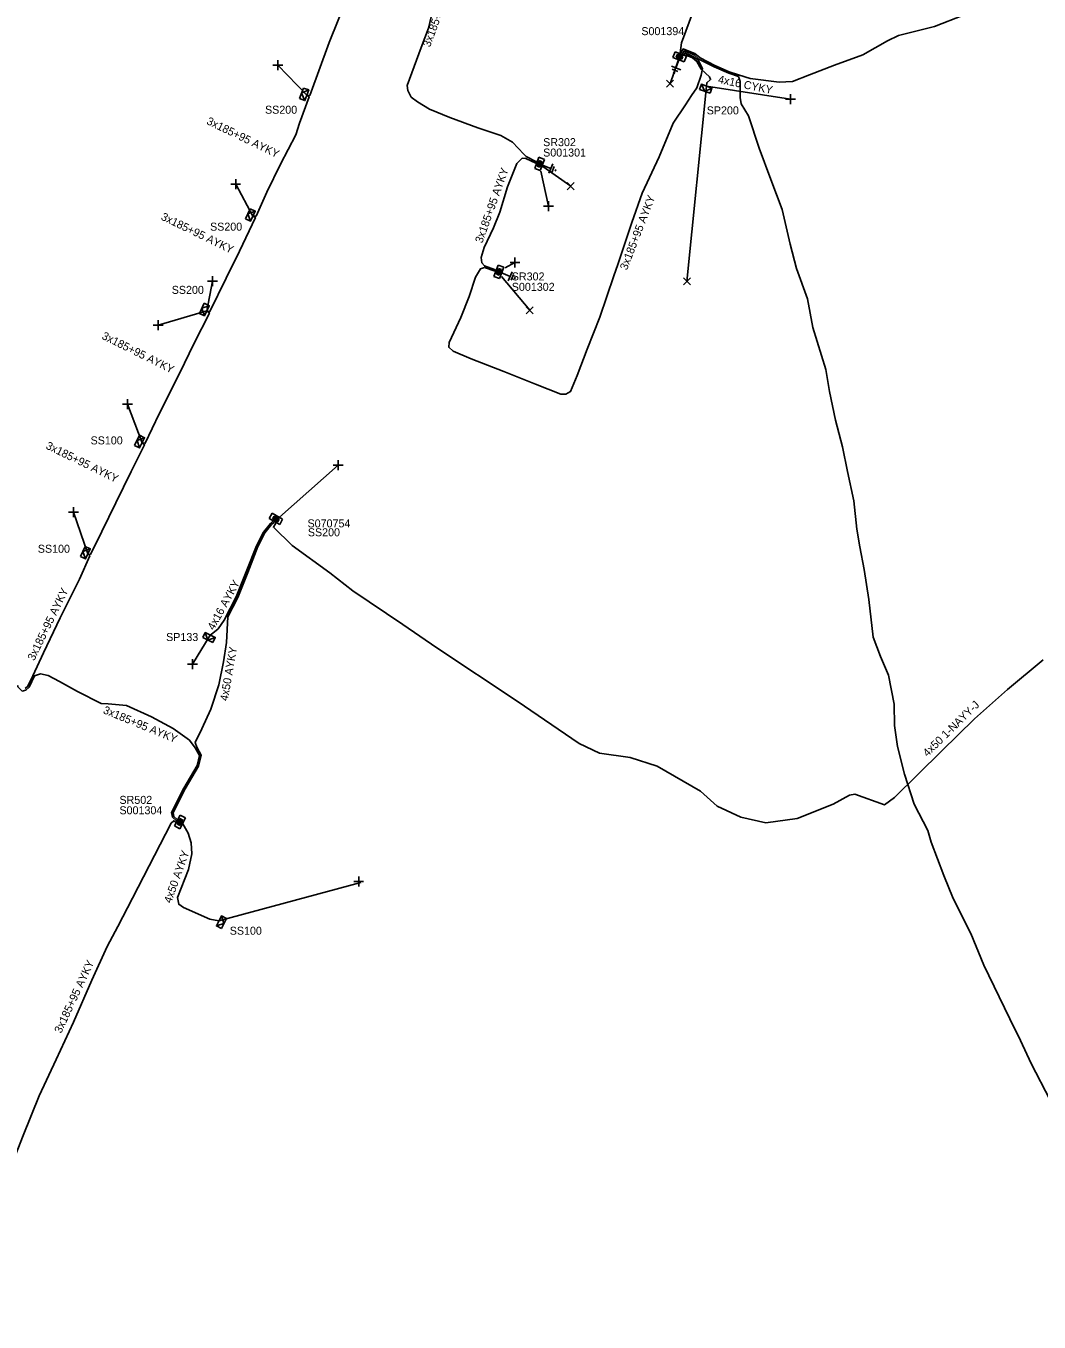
# Model space of a CAD drawing. Extents: x -763093 to -760976, y -1155572 to -1152009.
# Drawn here: x -762038.5 to -761911.9, y -1155041.4 to -1154879.5 of the extents above; entities that cross this region are included whole.
import ezdxf

# ---------------------------------------------------------------- set-up
doc = ezdxf.new("R2010")
doc.units = 0
for name, color, linetype in [('Vrstva 1', 7, 'Continuous'), ('Vrstva 14', 7, 'Continuous'), ('Vrstva 15', 7, 'Continuous'), ('Vrstva 28', 7, 'Continuous'), ('Vrstva 29', 7, 'Continuous'), ('Vrstva 30', 7, 'Continuous'), ('Vrstva 31', 7, 'Continuous'), ('Vrstva 33', 7, 'Continuous'), ('Vrstva 34', 7, 'Continuous'), ('Vrstva 5', 7, 'Continuous'), ('Vrstva 52', 7, 'Continuous'), ('Vrstva 54', 7, 'Continuous'), ('Vrstva 59', 7, 'Continuous'), ('Vrstva 6', 7, 'Continuous'), ('Vrstva 8', 7, 'Continuous'), ('Vrstva 9', 7, 'Continuous')]:
    doc.layers.add(name, color=color, linetype=linetype)

# ---------------------------------------------------------------- blocks, each defined once
blk = doc.blocks.new('NN800')
at = {"layer": 'Vrstva 1'}
for points in [[(-0.44, 0.44), (0.44, -0.44)], [(-0.44, -0.44), (0.44, 0.44)]]:
    blk.add_lwpolyline(points, dxfattribs=at)
blk = doc.blocks.new('NN620')
at = {"layer": 'Vrstva 8'}
for points in [[(0.75, 0), (-0.75, 0)], [(-0.75, 0), (-0.75, -0.75)], [(0.75, -0.75), (0.75, 0)], [(-0.75, -0.75), (0.75, -0.75)], [(0.37, -0.18), (-0.38, -0.18)], [(-0.38, -0.18), (-0.38, -0.56)], [(-0.38, -0.56), (0.37, -0.56)], [(0.32, -0.23), (-0.33, -0.23)], [(-0.33, -0.23), (-0.33, -0.51)], [(-0.33, -0.51), (0.32, -0.51)], [(0.27, -0.27), (-0.28, -0.27)], [(-0.28, -0.27), (-0.28, -0.46)], [(-0.28, -0.46), (0.27, -0.46)], [(0.23, -0.32), (-0.23, -0.32)], [(-0.23, -0.32), (-0.23, -0.42)], [(-0.23, -0.42), (0.23, -0.42)], [(-0.19, -0.37), (0.19, -0.37)], [(0.23, -0.42), (0.23, -0.32)], [(0.27, -0.46), (0.27, -0.27)], [(0.32, -0.51), (0.32, -0.23)], [(0.37, -0.56), (0.37, -0.18)]]:
    blk.add_lwpolyline(points, dxfattribs=at)
blk = doc.blocks.new('NN630')
at = {"layer": 'Vrstva 9'}
for points in [[(0, -0.7), (-0.7, 0)], [(-0.7, -0.7), (-0.7, 0), (0.7, 0), (0.7, -0.7)], [(-0.7, -0.7), (0.7, -0.7)], [(0, -0.7), (0.7, 0)]]:
    blk.add_lwpolyline(points, dxfattribs=at)
blk = doc.blocks.new('NN810')
at = {"layer": 'Vrstva 14'}
for points in [[(0, -0.64), (0, -1.89)], [(0.63, -1.89), (-0.62, -1.89)], [(0.39, -2.2), (-0.4, -2.2)], [(0, -2.52), (-0.12, -2.52)], [(0.14, -2.52), (0, -2.52)]]:
    blk.add_lwpolyline(points, dxfattribs=at)

msp = doc.modelspace()

# ---------------------------------------------------------------- linework, layer by layer
at = {"layer": 'Vrstva 5'}
for points in [[(-761974.73, -1154896.45), (-761976.02, -1154895.81), (-761976.32, -1154895.51), (-761977.72, -1154894), (-761979.19, -1154893.19), (-761982.07, -1154892.21), (-761985.55, -1154890.91), (-761988.08, -1154889.86), (-761989.57, -1154888.98), (-761990.38, -1154888.36), (-761990.79, -1154887.53), (-761990.9, -1154886.94), (-761989.13, -1154882.18), (-761988.22, -1154879.75), (-761987.67, -1154877.45), (-761987.55, -1154876.02), (-761986.41, -1154872.5), (-761984.64, -1154867.37), (-761984.51, -1154867.33)], [(-761953.59, -1154873.47), (-761956.61, -1154881.61), (-761956.77, -1154882.82)], [(-761956.76, -1154882.91), (-761956.39, -1154882.34), (-761954.93, -1154882.94), (-761954.29, -1154883.46), (-761952.44, -1154884.41), (-761950.63, -1154885.21), (-761949.5, -1154885.6), (-761948.02, -1154886.05), (-761944.39, -1154886.5), (-761942.75, -1154886.42), (-761940.62, -1154885.57), (-761937.48, -1154884.38), (-761933.96, -1154883.07), (-761930.85, -1154881.32), (-761929.51, -1154880.69), (-761924.98, -1154879.55), (-761921.37, -1154878.15), (-761917.08, -1154876.64), (-761913.14, -1154874.9), (-761909.53, -1154873.22)], [(-762038.62, -1154962.29), (-762038.28, -1154962), (-762037.67, -1154960.67), (-762036.31, -1154957.82), (-762034.25, -1154953.43), (-762031.84, -1154948.59), (-762030.54, -1154945.69), (-762030.77, -1154945.44), (-762030.46, -1154945.51), (-762029.04, -1154942.66), (-762027.29, -1154939.07), (-762025.35, -1154935.17), (-762023.69, -1154931.81), (-762024, -1154931.57), (-762023.61, -1154931.63), (-762021.86, -1154927.96), (-762019.29, -1154922.81), (-762017.53, -1154919.2), (-762015.6, -1154915.35), (-762015.91, -1154915.07), (-762015.52, -1154915.17), (-762013.49, -1154911), (-762011.84, -1154907.64), (-762009.84, -1154903.41), (-762010.16, -1154903.25), (-762009.76, -1154903.23), (-762008.43, -1154900.25), (-762006.69, -1154896.74), (-762004.79, -1154893.07), (-762004.33, -1154891.63), (-762003.12, -1154888.34), (-762003.42, -1154888.14), (-762003.06, -1154888.16), (-762000.61, -1154881.53), (-761998.29, -1154875.7)], [(-761979.77, -1154910.07), (-761980.01, -1154910.09), (-761981.22, -1154909.65), (-761981.7, -1154909.83), (-761982.33, -1154910.89), (-761983.14, -1154913.28), (-761984.18, -1154915.92), (-761985.65, -1154919.02), (-761985.69, -1154919.64), (-761985.14, -1154920.13), (-761982.87, -1154921.06), (-761978.81, -1154922.64), (-761974.86, -1154924.23), (-761971.7, -1154925.51), (-761971.05, -1154925.5), (-761970.47, -1154925.16), (-761969.62, -1154923.17), (-761968.39, -1154919.89), (-761966.82, -1154915.85), (-761965.05, -1154910.71), (-761964.55, -1154909.27), (-761962.83, -1154904.06), (-761961.5, -1154900.37), (-761959.38, -1154895.82), (-761957.66, -1154891.63), (-761956.09, -1154889.33), (-761955.36, -1154888.18), (-761954.68, -1154887.23), (-761954.16, -1154885.64), (-761953.96, -1154884.8), (-761954.54, -1154883.77), (-761955.13, -1154883.29), (-761956.19, -1154882.86), (-761956.33, -1154883.07)], [(-761956.14, -1154883.15), (-761956.11, -1154883.11), (-761955.23, -1154883.46), (-761954.67, -1154883.92), (-761954.14, -1154884.88), (-761953.1, -1154885.82), (-761952.96, -1154886.19), (-761953.44, -1154886.58), (-761953.46, -1154887)], [(-761979.77, -1154910.07), (-761979.95, -1154909.9), (-761981.22, -1154909.44), (-761981.55, -1154909.08), (-761981.63, -1154908.4), (-761981.28, -1154907.17), (-761980.11, -1154904.7), (-761979.3, -1154902.77), (-761978.36, -1154899.58), (-761977.18, -1154896.68), (-761976.52, -1154896.02), (-761976.04, -1154896.03), (-761974.81, -1154896.64)], [(-762019.61, -1154978.63), (-762020.04, -1154978.25), (-762020.12, -1154977.8), (-762018.6, -1154974.83), (-762016.95, -1154971.99), (-762016.61, -1154970.61), (-762017.18, -1154969.62), (-762017.37, -1154969.01), (-762016.52, -1154967.33), (-762015.4, -1154964.85), (-762014.42, -1154961.81), (-762013.85, -1154958.92), (-762013.47, -1154956.51), (-762013.3, -1154953.31), (-762012.06, -1154950.89), (-762010.81, -1154947.76), (-762009.54, -1154944.51), (-762008.66, -1154942.83), (-762007.82, -1154941.78), (-762007.51, -1154941.5)], [(-762015.49, -1154955.59), (-762015.15, -1154955.34), (-762014.48, -1154954.81), (-762013.74, -1154953.73), (-762012.25, -1154950.83), (-762010.99, -1154947.68), (-762009.72, -1154944.43), (-762008.82, -1154942.73), (-762007.96, -1154941.64), (-762007.89, -1154941.57), (-762007.67, -1154941.38)], [(-762039.5, -1154961.9), (-762039.57, -1154962.01), (-762039, -1154962.59), (-762038.52, -1154962.47), (-762038.12, -1154962.12), (-762037.45, -1154960.67), (-762036.71, -1154960.42), (-762035.72, -1154960.66), (-762034.33, -1154961.38), (-762032.07, -1154962.66), (-762029.12, -1154964.13), (-762028.23, -1154964.18), (-762025.96, -1154964.41), (-762022.84, -1154965.82), (-762020.14, -1154967.27), (-762018.08, -1154968.71), (-762017.37, -1154969.7), (-762016.83, -1154970.65), (-762017.13, -1154971.91), (-762018.78, -1154974.73), (-762020.32, -1154977.76), (-762020.22, -1154978.35), (-762019.7, -1154978.82)], [(-762048.47, -1155043.02), (-762046.66, -1155038.38), (-762044.82, -1155033.57), (-762042.9, -1155028.86), (-762041.22, -1155024.21), (-762038.87, -1155018.14), (-762036.88, -1155013.17), (-762034.76, -1155008.65), (-762032.58, -1155003.98), (-762030.27, -1154998.71), (-762028.37, -1154994.51), (-762027.03, -1154992.02), (-762025.2, -1154988.46), (-762020.35, -1154979.1), (-762020.05, -1154978.79), (-762019.77, -1154978.99)], [(-762018.93, -1154979.18), (-762018.23, -1154980.33), (-762017.89, -1154981.56), (-762017.8, -1154982.95), (-762018.22, -1154984.91), (-762019.57, -1154988.41), (-762019.43, -1154989.23), (-762018.84, -1154989.63), (-762015.55, -1154991.09), (-762014.41, -1154991.31)]]:
    msp.add_lwpolyline(points, dxfattribs=at)
at = {"layer": 'Vrstva 52'}
msp.add_lwpolyline([(-762007.25, -1154941.54), (-762007.59, -1154942.13), (-762005.24, -1154944.42), (-762000.54, -1154947.82), (-761997.69, -1154950.08), (-761991.43, -1154954.26), (-761987.17, -1154957.2), (-761977.12, -1154963.85), (-761969.38, -1154969.13), (-761966.87, -1154970.37), (-761963.03, -1154970.9), (-761959.66, -1154971.99), (-761954.24, -1154975.09), (-761952.13, -1154976.97), (-761949.2, -1154978.35), (-761946.06, -1154979.07), (-761942.17, -1154978.53), (-761937.64, -1154976.71), (-761935.61, -1154975.59), (-761934.96, -1154975.49), (-761931.24, -1154976.79), (-761929.98, -1154975.88), (-761924.1, -1154970.12), (-761920.01, -1154966.08), (-761915.86, -1154962.39), (-761911.4, -1154958.7)], dxfattribs=at)
at = {"layer": 'Vrstva 59'}
for points in [[(-762003.42, -1154888.14), (-762007.06, -1154884.38)], [(-761957.01, -1154883.81), (-761958.03, -1154886.7)], [(-761953.46, -1154887), (-761955.92, -1154911.4)], [(-761953.46, -1154887), (-761943, -1154888.63)], [(-761974.18, -1154897.61), (-761973.22, -1154902.01)], [(-761973.91, -1154897.03), (-761970.44, -1154899.5)], [(-762010.16, -1154903.25), (-762012.31, -1154899.25)], [(-761978.65, -1154909.72), (-761977.41, -1154909.05)], [(-761979.1, -1154910.77), (-761975.56, -1154915)], [(-762015.91, -1154915.07), (-762015.21, -1154911.38)], [(-762015.91, -1154915.07), (-762022, -1154916.88)], [(-762024, -1154931.57), (-762025.81, -1154926.75)], [(-762006.85, -1154940.86), (-761999.5, -1154934.38)], [(-762030.77, -1154945.44), (-762032.56, -1154940.25)], [(-762015.49, -1154955.59), (-762017.72, -1154959.25)], [(-762014.41, -1154991.31), (-761996.67, -1154986.51)]]:
    msp.add_lwpolyline(points, dxfattribs=at)
at = {"layer": 'Vrstva 9'}
msp.add_lwpolyline([(-761956.52, -1154882.97), (-761956.28, -1154882.61), (-761955.03, -1154883.11), (-761954.42, -1154883.61), (-761952.52, -1154884.59), (-761950.71, -1154885.39), (-761949.49, -1154885.81), (-761949.28, -1154886.42), (-761949.28, -1154888.42), (-761949.15, -1154889.21), (-761948.23, -1154890.72), (-761946.9, -1154894.74), (-761945.45, -1154898.66), (-761944.02, -1154902.41), (-761943.02, -1154906.73), (-761942.23, -1154909.78), (-761940.87, -1154913.56), (-761940.21, -1154917.16), (-761938.57, -1154922.42), (-761938.11, -1154925.14), (-761937.38, -1154928.73), (-761936.47, -1154932.07), (-761935.88, -1154935.14), (-761935.06, -1154938.82), (-761934.68, -1154942.35), (-761934.34, -1154944.56), (-761933.79, -1154947.41), (-761933.19, -1154951.16), (-761932.64, -1154955.84), (-761931.72, -1154958.29), (-761930.74, -1154960.62), (-761930.03, -1154964.24), (-761929.98, -1154966.91), (-761929.63, -1154969.54), (-761928.72, -1154972.96), (-761927.55, -1154976.72), (-761925.83, -1154980.03), (-761925.39, -1154981.49), (-761923.82, -1154985.66), (-761922.64, -1154988.5), (-761920.45, -1154992.9), (-761918.82, -1154996.84), (-761916.91, -1155000.81), (-761915.56, -1155003.56), (-761914.24, -1155006.24), (-761912.93, -1155009.14), (-761910.54, -1155013.72)], dxfattribs=at)

# ---------------------------------------------------------------- block references
at = {"layer": 'Vrstva 15'}
for p, rotation in [((-761956.61, -1154882.96), -21.18706123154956), ((-761974.68, -1154896.59), 68.01475553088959), ((-761979.77, -1154910.07), 68.17776944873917)]:
    msp.add_blockref('NN810', p, dxfattribs=dict(at, rotation=rotation))
at = {"layer": 'Vrstva 28'}
for p, rotation in [((-761956.7, -1154882.99), -20.859961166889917), ((-761974.68, -1154896.59), 69.35043834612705), ((-761979.77, -1154910.07), 68.78385000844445), ((-762007.46, -1154941.4), 150.68999166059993), ((-762019.6, -1154978.78), 62.94315283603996)]:
    msp.add_blockref('NN620', p, dxfattribs=dict(at, rotation=rotation))
at = {"layer": 'Vrstva 31'}
for p, rotation in [((-761953.46, -1154887), -19.580859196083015), ((-762003.42, -1154888.14), -110.18468059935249), ((-762010.16, -1154903.25), -115.93255558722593), ((-762015.91, -1154915.07), -115.93255552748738), ((-762024, -1154931.57), -115.94291108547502), ((-762030.77, -1154945.44), -114.37115145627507), ((-762015.49, -1154955.59), -25.793149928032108), ((-762014.41, -1154991.31), 63.191864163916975)]:
    msp.add_blockref('NN630', p, dxfattribs=dict(at, rotation=rotation))
at = {"layer": 'Vrstva 34'}
for p, rotation in [((-762007.06, -1154884.38), 45), ((-761943, -1154888.63), 45), ((-762012.31, -1154899.25), 45), ((-761973.22, -1154902.01), 45), ((-761977.41, -1154909.05), 45), ((-762015.21, -1154911.38), 45), ((-762022, -1154916.88), 45), ((-762025.81, -1154926.75), 45), ((-761999.5, -1154934.38), 45), ((-762032.56, -1154940.25), 45), ((-762017.72, -1154959.25), 45), ((-761996.94, -1154986.38), 44.99999995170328)]:
    msp.add_blockref('NN800', p, dxfattribs=dict(at, rotation=rotation))
for p in [(-761958.03, -1154886.7), (-761970.44, -1154899.5), (-761955.92, -1154911.4), (-761975.56, -1154915)]:
    msp.add_blockref('NN800', p, dxfattribs=at)

# ---------------------------------------------------------------- texts
at = {"layer": 'Vrstva 29'}
for s, p in [('S001394', (-761961.62, -1154880.63)), ('S001301', (-761973.89, -1154895.8)), ('S001302', (-761977.81, -1154912.58)), ('S070754', (-762003.33, -1154942.14)), ('S001304', (-762026.83, -1154977.99))]:
    msp.add_text(s, height=1, dxfattribs=at).set_placement(p)
at = {"layer": 'Vrstva 30'}
for s, p in [('SR302', (-761973.89, -1154894.5)), ('SR302', (-761977.81, -1154911.28)), ('SS200', (-762003.29, -1154943.25)), ('SR502', (-762026.83, -1154976.69))]:
    msp.add_text(s, height=1, dxfattribs=at).set_placement(p)
at = {"layer": 'Vrstva 33'}
for s, p in [('SS200', (-762008.64, -1154890.45)), ('SP200', (-761953.45, -1154890.53)), ('SS200', (-762015.51, -1154905.06)), ('SS200', (-762020.3, -1154912.96)), ('SS100', (-762030.44, -1154931.77)), ('SS100', (-762037.03, -1154945.31)), ('SP133', (-762021, -1154956.34)), ('SS100', (-762013.05, -1154993.04))]:
    msp.add_text(s, height=1, dxfattribs=at).set_placement(p)
at = {"layer": 'Vrstva 54'}
msp.add_text('4x50 1-NAYY-J', height=1, rotation=44.409, dxfattribs=at).set_placement((-761925.87, -1154970.87))
at = {"layer": 'Vrstva 6'}
for s, rotation, p in [('3x185+95 AYKY', 69.754, (-761988.03, -1154882.2)), ('4x16 CYKY', 348.318, (-761952.1, -1154886.6)), ('3x185+95 AYKY', 334.083, (-762016.03, -1154891.7)), ('3x185+95 AYKY', 70.357, (-761981.5, -1154906.7)), ('3x185+95 AYKY', 68.826, (-761963.42, -1154910.06)), ('3x185+95 AYKY', 334.033, (-762021.73, -1154903.64)), ('3x185+95 AYKY', 333.451, (-762029.13, -1154918.53)), ('3x185+95 AYKY', 333.944, (-762036.12, -1154932.26)), ('3x185+95 AYKY', 64.125, (-762037.48, -1154958.88)), ('4x16 AYKY', 61.254, (-762015.03, -1154955.06)), ('4x50 AYKY', 80.064, (-762013.3, -1154963.89)), ('3x185+95 AYKY', 337.479, (-762028.96, -1154965.33)), ('4x50 AYKY', 70.387, (-762020.38, -1154989.18)), ('3x185+95 AYKY', 65.056, (-762034.12, -1155005.44))]:
    msp.add_text(s, height=1, rotation=rotation, dxfattribs=at).set_placement(p)

doc.saveas('drawing.dxf')
